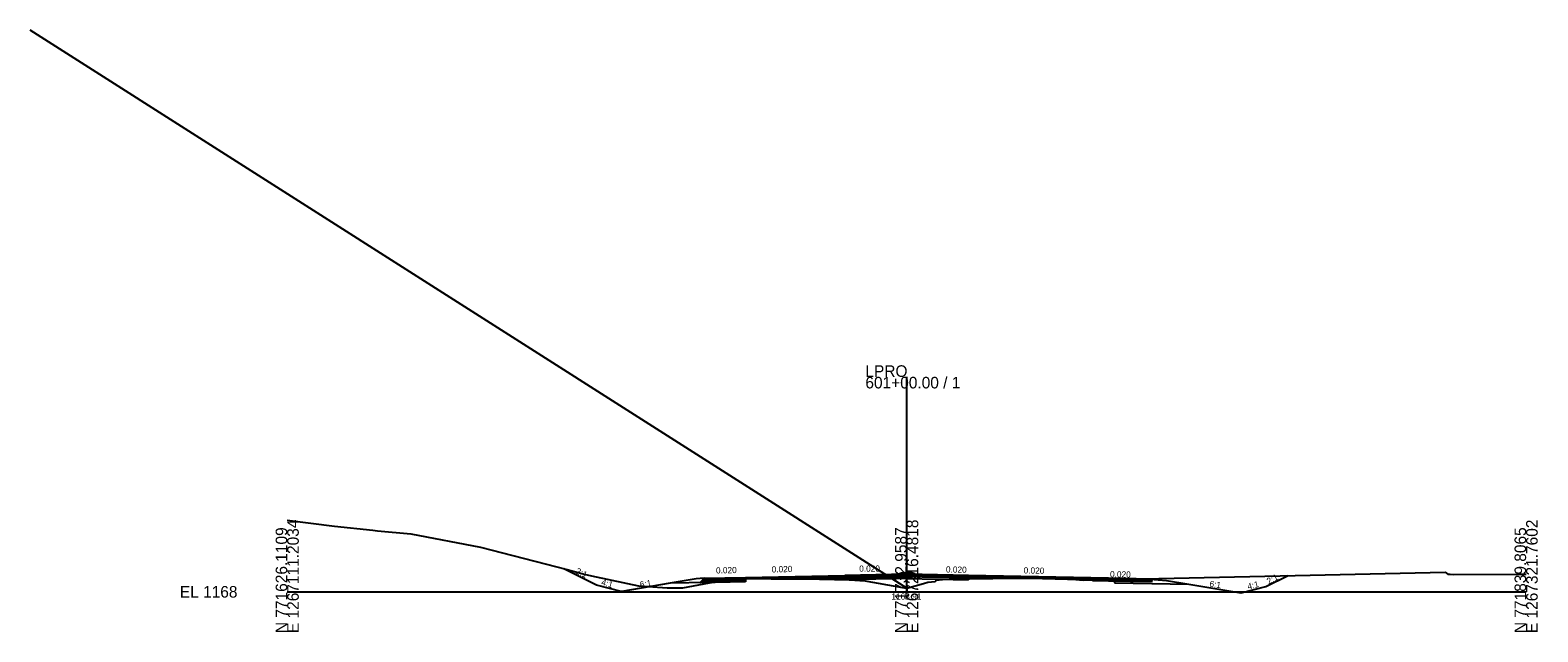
# Model space of a CAD drawing. Extents: x -3833 to 1267678, y -522 to 773248.
# Drawn here: x 937.8 to 1302.8, y 1990.3 to 2136 of the extents above; entities that cross this region are included whole.
import ezdxf

# ---------------------------------------------------------------- set-up
doc = ezdxf.new("R2010")
doc.units = 0
for name, color, linetype in [('Exist Cross Section Cell', 7, 'Continuous'), ('Exist XS Center Line Elevation Label', 7, 'Continuous'), ('Exist XS Ground Line', 7, 'Continuous'), ('Prop CMT DNC', 7, 'Continuous'), ('Prop CMT Pvmt Course 1', 7, 'Continuous'), ('Prop CMT Pvmt Course 2', 7, 'Continuous'), ('Prop CMT Pvmt Course 4', 7, 'Continuous'), ('Prop CMT Shld Paved Course 1', 7, 'Continuous'), ('Prop CMT Shld Paved Course 2', 7, 'Continuous'), ('Prop CMT Shld Paved Course 4', 7, 'Continuous'), ('Prop CMT Slope Grass', 7, 'Continuous'), ('Prop CMT Subgrade Earthwork', 7, 'Continuous'), ('Prop Conc Curb and Gutter', 7, 'Continuous'), ('Prop Corridor Mesh Bottom', 7, 'Continuous'), ('Prop XS Ditch Slope Text', 7, 'Continuous'), ('Prop XS Finish Grade', 7, 'Continuous'), ('Prop XS SE Text', 7, 'Continuous'), ('Scratch_Level_1', 7, 'Continuous')]:
    doc.layers.add(name, color=color, linetype=linetype)

msp = doc.modelspace()

# ---------------------------------------------------------------- linework, layer by layer
at = {"layer": 'Exist Cross Section Cell'}
for p, q in [((1150, 2000), (1150, 2052.04)), ((1000, 2000), (1150, 2000)), ((1150, 2000), (1300, 2000))]:
    msp.add_line(p, q, dxfattribs=at)
at = {"layer": 'Exist XS Ground Line'}
for p, q in [((1000, 2017.35), (1011.44, 2015.88)), ((1011.44, 2015.88), (1020.77, 2014.9)), ((1020.77, 2014.9), (1021.86, 2014.79)), ((1021.86, 2014.79), (1029.97, 2014.07)), ((1029.97, 2014.07), (1046.78, 2010.8)), ((1046.78, 2010.8), (1067.76, 2005.37)), ((1067.76, 2005.37), (1072.22, 2004.2)), ((1244.09, 2003.95), (1280.38, 2004.73)), ((1280.38, 2004.73), (1281.05, 2004.27)), ((1072.22, 2004.2), (1074.82, 2003.59)), ((1074.82, 2003.59), (1085.03, 2001.42)), ((1085.03, 2001.42), (1092.03, 2001)), ((1092.03, 2001), (1095.8, 2000.95)), ((1095.8, 2000.95), (1100.99, 2001.9)), ((1100.99, 2001.9), (1106.65, 2003)), ((1106.65, 2003), (1108.56, 2003.11)), ((1108.56, 2003.11), (1110.7, 2003.22)), ((1110.7, 2003.22), (1117.21, 2003.18)), ((1117.21, 2003.18), (1122.68, 2003.14)), ((1122.68, 2003.14), (1128.9, 2003.02)), ((1128.9, 2003.02), (1136.08, 2002.89)), ((1136.08, 2002.89), (1137.47, 2002.83)), ((1137.47, 2002.83), (1138.69, 2002.77)), ((1138.69, 2002.77), (1139.47, 2002.73)), ((1139.47, 2002.73), (1148.99, 2001.08)), ((1148.99, 2001.08), (1150.04, 2000.91)), ((1150.04, 2000.91), (1154.1, 2002.03)), ((1154.1, 2002.03), (1155.09, 2002.3)), ((1155.09, 2002.3), (1156.87, 2002.53)), ((1156.87, 2002.53), (1157.17, 2002.85)), ((1157.17, 2002.85), (1158.71, 2002.94)), ((1158.71, 2002.94), (1160.29, 2003.02)), ((1160.29, 2003.02), (1162.74, 2003.09)), ((1162.74, 2003.09), (1164.92, 2003.16)), ((1164.92, 2003.16), (1170.4, 2003.25)), ((1170.4, 2003.25), (1176.81, 2003.34)), ((1176.81, 2003.34), (1179.94, 2003.28)), ((1179.94, 2003.28), (1188.92, 2003.09)), ((1188.92, 2003.09), (1190.93, 2002.96)), ((1190.93, 2002.96), (1192.71, 2002.85)), ((1192.71, 2002.85), (1244.09, 2003.95)), ((1281.05, 2004.27), (1281.6, 2004.26)), ((1281.6, 2004.26), (1282.41, 2004.21)), ((1282.41, 2004.21), (1298.02, 2004.28)), ((1298.02, 2004.28), (1300, 2004.3))]:
    msp.add_line(p, q, dxfattribs=at)
at = {"layer": 'Prop CMT Pvmt Course 1'}
for p, q in [((1111, 2003.47), (1135, 2003.95)), ((1135, 2003.7), (1111, 2003.22)), ((1111, 2003.22), (1111, 2003.47)), ((1111, 2003.47), (1111, 2003.47)), ((1135, 2003.95), (1135, 2003.95)), ((1135, 2003.95), (1135, 2003.95)), ((1135, 2003.95), (1135, 2003.7)), ((1135, 2003.7), (1135, 2003.7)), ((1147.75, 2004.21), (1147, 2004.19)), ((1147, 2003.94), (1147.75, 2003.96)), ((1152.25, 2004.21), (1152.82, 2004.2)), ((1152.82, 2003.95), (1152.25, 2003.96)), ((1152.82, 2004.2), (1153, 2004.19)), ((1153, 2003.94), (1152.82, 2003.95)), ((1198.91, 2003.27), (1165, 2003.95)), ((1165, 2003.95), (1165, 2003.95)), ((1165, 2003.95), (1165, 2003.7)), ((1165, 2003.7), (1195, 2003.1)), ((1165, 2003.7), (1165, 2003.7)), ((1195, 2003.1), (1195, 2003.35)), ((1195, 2003.35), (1195, 2003.35)), ((1195, 2003.35), (1198.91, 2003.27)), ((1198.91, 2003.27), (1198.91, 2003.27)), ((1198.91, 2003.27), (1198.91, 2003.27))]:
    msp.add_line(p, q, dxfattribs=at)
at = {"layer": 'Prop CMT Pvmt Course 2'}
for p, q in [((1150, 2004), (1135, 2003.7)), ((1135, 2003.7), (1135, 2003.7)), ((1135, 2003.7), (1135, 2003.37)), ((1135, 2003.37), (1150, 2003.67)), ((1135, 2003.37), (1135, 2003.37)), ((1147.75, 2003.96), (1147, 2003.94)), ((1165, 2003.7), (1150, 2004)), ((1150, 2004), (1150, 2004)), ((1150, 2004), (1150, 2004)), ((1150, 2003.67), (1150, 2003.67)), ((1150, 2003.67), (1150, 2003.67)), ((1150, 2003.67), (1165, 2003.37)), ((1152.25, 2003.96), (1152.82, 2003.95)), ((1152.82, 2003.95), (1153, 2003.94)), ((1165, 2003.37), (1165, 2003.7)), ((1165, 2003.7), (1165, 2003.7)), ((1165, 2003.37), (1165, 2003.37)), ((1195, 2003.1), (1195, 2002.77)), ((1198.91, 2003.02), (1195, 2003.1)), ((1195, 2002.77), (1198.91, 2002.69)), ((1198.91, 2002.69), (1198.91, 2003.02))]:
    msp.add_line(p, q, dxfattribs=at)
at = {"layer": 'Prop CMT Pvmt Course 4'}
for p, q in [((1135, 2003.37), (1150, 2003.67)), ((1135, 2003.37), (1135, 2003.37)), ((1135, 2003.37), (1135, 2003.37)), ((1147.01, 2004.19), (1147.01, 2003.15)), ((1148.01, 2004.21), (1148.01, 2003.17)), ((1150, 2003.67), (1150, 2003.67)), ((1150, 2003.67), (1150, 2003.67)), ((1150, 2003.67), (1165, 2003.37)), ((1152.01, 2004.21), (1152.01, 2003.17)), ((1153.01, 2004.19), (1153.01, 2003.15)), ((1165, 2003.37), (1165, 2003.37)), ((1165, 2003.37), (1165, 2003.37))]:
    msp.add_line(p, q, dxfattribs=at)
at = {"layer": 'Prop CMT Shld Paved Course 1'}
for p, q in [((1100.74, 2003.02), (1101, 2003.27)), ((1111, 2003.22), (1100.74, 2003.02)), ((1101, 2003.27), (1111, 2003.47)), ((1101, 2003.27), (1101, 2003.27)), ((1111, 2003.47), (1111, 2003.47)), ((1111, 2003.47), (1111, 2003.47)), ((1111, 2003.47), (1111, 2003.22)), ((1111, 2003.22), (1111, 2003.22)), ((1150, 2004.25), (1135, 2003.95)), ((1135, 2003.7), (1150, 2004)), ((1135, 2003.95), (1135, 2003.95)), ((1135, 2003.95), (1135, 2003.7)), ((1165, 2003.95), (1150, 2004.25)), ((1150, 2004.25), (1150, 2004.25)), ((1150, 2004.25), (1150, 2004.25)), ((1150, 2004), (1150, 2004)), ((1150, 2004), (1150, 2004)), ((1150, 2004), (1165, 2003.7)), ((1150, 2003.94), (1150, 2003.94)), ((1165, 2003.7), (1165, 2003.95)), ((1165, 2003.95), (1165, 2003.95)), ((1198.91, 2003.27), (1198.91, 2003.02)), ((1208.91, 2003.07), (1198.91, 2003.27)), ((1198.91, 2003.02), (1209.17, 2002.82)), ((1209.17, 2002.82), (1208.91, 2003.07))]:
    msp.add_line(p, q, dxfattribs=at)
at = {"layer": 'Prop CMT Shld Paved Course 2'}
for p, q in [((1100.4, 2002.68), (1100.74, 2003.02)), ((1111, 2002.89), (1100.4, 2002.68)), ((1100.74, 2003.02), (1111, 2003.22)), ((1100.74, 2003.02), (1100.74, 2003.02)), ((1117.21, 2003.35), (1111, 2003.22)), ((1111, 2003.22), (1111, 2003.22)), ((1111, 2003.22), (1111, 2003.22)), ((1111, 2003.22), (1111, 2003.22)), ((1111, 2003.22), (1111, 2003.22)), ((1111, 2003.22), (1111, 2003.22)), ((1111, 2003.22), (1117.21, 2003.18)), ((1111, 2002.89), (1111, 2002.89)), ((1122.67, 2003.46), (1117.21, 2003.35)), ((1117.21, 2003.35), (1117.21, 2003.35)), ((1117.21, 2003.18), (1117.21, 2003.18)), ((1117.21, 2003.18), (1122.67, 2003.14)), ((1128.9, 2003.58), (1122.67, 2003.46)), ((1122.67, 2003.14), (1122.67, 2003.14)), ((1122.67, 2003.14), (1123.18, 2003.13)), ((1123.18, 2003.13), (1128.9, 2003.25)), ((1135, 2003.7), (1128.9, 2003.58)), ((1128.9, 2003.58), (1128.9, 2003.58)), ((1128.9, 2003.25), (1135, 2003.37)), ((1128.9, 2003.25), (1128.9, 2003.25)), ((1135, 2003.7), (1135, 2003.7)), ((1170.4, 2003.59), (1165, 2003.7)), ((1165, 2003.7), (1165, 2003.7)), ((1165, 2003.7), (1165, 2003.16)), ((1165, 2003.37), (1170.4, 2003.26)), ((1176.81, 2003.47), (1170.4, 2003.59)), ((1170.4, 2003.59), (1170.4, 2003.59)), ((1170.4, 2003.26), (1170.4, 2003.26)), ((1170.4, 2003.26), (1170.85, 2003.25)), ((1170.85, 2003.25), (1176.81, 2003.34)), ((1179.94, 2003.4), (1176.81, 2003.47)), ((1176.81, 2003.47), (1176.81, 2003.47)), ((1176.81, 2003.47), (1176.81, 2003.47)), ((1176.81, 2003.34), (1176.81, 2003.34)), ((1176.81, 2003.34), (1176.81, 2003.34)), ((1176.81, 2003.34), (1176.81, 2003.34)), ((1176.81, 2003.34), (1179.94, 2003.28)), ((1188.92, 2003.22), (1179.94, 2003.4)), ((1179.94, 2003.4), (1179.94, 2003.4)), ((1179.94, 2003.28), (1179.94, 2003.28)), ((1179.94, 2003.28), (1188.92, 2003.09)), ((1190.93, 2003.18), (1188.92, 2003.22)), ((1188.92, 2003.22), (1188.92, 2003.22)), ((1188.92, 2003.09), (1188.92, 2003.09)), ((1188.92, 2003.09), (1190.93, 2002.96)), ((1192.71, 2003.15), (1190.93, 2003.18)), ((1190.93, 2003.18), (1190.93, 2003.18)), ((1190.93, 2002.96), (1190.93, 2002.96)), ((1190.93, 2002.96), (1192.71, 2002.85)), ((1195, 2003.1), (1192.71, 2003.15)), ((1192.71, 2003.15), (1192.71, 2003.15)), ((1192.71, 2002.85), (1195, 2002.9)), ((1192.71, 2002.85), (1192.71, 2002.85)), ((1192.71, 2002.85), (1192.71, 2002.85)), ((1192.71, 2002.85), (1192.71, 2002.85)), ((1195, 2002.9), (1195, 2003.1)), ((1195, 2003.1), (1195, 2003.1)), ((1195, 2003.1), (1195, 2003.1)), ((1195, 2002.9), (1195, 2002.9)), ((1198.91, 2003.02), (1198.91, 2002.69)), ((1209.17, 2002.82), (1198.91, 2003.02)), ((1198.91, 2002.69), (1209.5, 2002.48)), ((1209.5, 2002.48), (1209.17, 2002.82))]:
    msp.add_line(p, q, dxfattribs=at)
at = {"layer": 'Prop CMT Shld Paved Course 4'}
for p, q in [((1099.94, 2002.21), (1100.4, 2002.68)), ((1111, 2002.43), (1099.94, 2002.21)), ((1100.4, 2002.68), (1100.9, 2002.69)), ((1100.9, 2002.69), (1111, 2002.89)), ((1111, 2002.89), (1111, 2002.43)), ((1200.3, 2002.67), (1200.3, 2002.21)), ((1200.3, 2002.21), (1200.3, 2002.21))]:
    msp.add_line(p, q, dxfattribs=at)
at = {"layer": 'Prop CMT Slope Grass'}
for p, q in [((1099, 2003.11), (1092.72, 2002.07)), ((1101, 2003.27), (1099, 2003.11)), ((1208.91, 2003.07), (1212.91, 2002.75)), ((1212.91, 2002.75), (1218.36, 2001.85))]:
    msp.add_line(p, q, dxfattribs=at)
at = {"layer": 'Prop CMT Subgrade Earthwork'}
for p, q in [((1111, 2002.43), (1092.72, 2002.07)), ((1111, 2003.22), (1111, 2002.43)), ((1150.01, 2003.21), (1135.04, 2002.91)), ((1149.99, 2003.21), (1165, 2002.91)), ((1165, 2003.16), (1165, 2002.91)), ((1200.3, 2003.01), (1200.3, 2002.21)), ((1200.3, 2002.21), (1218.36, 2001.85))]:
    msp.add_line(p, q, dxfattribs=at)
at = {"layer": 'Prop Conc Curb and Gutter'}
for p, q in [((1148, 2004.17), (1148.01, 2004.34)), ((1148.01, 2004.34), (1148.76, 2004.59)), ((1148.76, 2004.59), (1150.01, 2004.61)), ((1151.25, 2004.58), (1150.01, 2004.61)), ((1152, 2004.33), (1151.25, 2004.58)), ((1148, 2004.17), (1148, 2004.04)), ((1148, 2004.04), (1150.01, 2004.04)), ((1152.01, 2004.04), (1150.01, 2004.04)), ((1152.01, 2004.17), (1152, 2004.33)), ((1152.01, 2004.17), (1152.01, 2004.04))]:
    msp.add_line(p, q, dxfattribs=at)
at = {"layer": 'Prop Corridor Mesh Bottom'}
for p, q in [((1111, 2003.47), (1111, 2003.22)), ((1135, 2003.95), (1135, 2003.7)), ((1165, 2003.95), (1165, 2003.7)), ((1198.91, 2003.27), (1198.91, 2003.02))]:
    msp.add_line(p, q, dxfattribs=at)
at = {"layer": 'Prop XS Finish Grade'}
for p, q in [((1074.9, 2001.61), (1066.98, 2005.57)), ((1080.9, 2000.11), (1074.9, 2001.61)), ((1092.72, 2002.07), (1081, 2000.11)), ((1208.91, 2003.07), (1212.91, 2002.75)), ((1218.36, 2001.85), (1230.91, 1999.75)), ((1231.01, 1999.75), (1237.01, 2001.25)), ((1237.01, 2001.25), (1242.34, 2003.92)), ((1080.95, 2000.11), (1080.9, 2000.11)), ((1081, 2000.11), (1080.95, 2000.11)), ((1230.91, 1999.75), (1230.96, 1999.75)), ((1230.96, 1999.75), (1231.01, 1999.75))]:
    msp.add_line(p, q, dxfattribs=at)
at = {"layer": 'Scratch_Level_1'}
msp.add_line((1150, 2000.91), (937.75, 2135.97), dxfattribs=at)

# ---------------------------------------------------------------- texts
at = {"layer": 'Exist Cross Section Cell'}
for s, p in [('601+00.00 / 1', (1140, 2049.24)), ('LPRO', (1140, 2052.04)), ('EL 1168', (974, 1998.6))]:
    msp.add_text(s, height=2.8, dxfattribs=at).set_placement(p)
for s, p in [('N 771626.1109', (1000, 1990)), ('E 1267111.2034', (1002.8, 1990)), ('N 771732.9587', (1150, 1990)), ('E 1267216.4818', (1152.8, 1990)), ('N 771839.8065', (1300, 1990)), ('E 1267321.7602', (1302.8, 1990))]:
    msp.add_text(s, height=2.8, rotation=90, dxfattribs=at).set_placement(p)
at = {"layer": 'Exist XS Center Line Elevation Label'}
msp.add_text('1168.91', height=1.5, dxfattribs=at).set_placement((1146.3, 1998.12))
at = {"layer": 'Prop CMT DNC'}
for p in [(1062.18, 2006.81), (1101, 2003.27), (1111, 2003.47), (1111, 2003.47), (1135, 2003.95), (1135, 2003.95), (1165, 2003.95), (1165, 2003.95), (1198.91, 2003.27), (1198.91, 2003.27), (1208.91, 2003.07), (1242.34, 2003.92), (1080.95, 2000.11), (1081, 2000.11), (1230.91, 1999.75), (1230.96, 1999.75)]:
    msp.add_text('X', height=0.00025, dxfattribs=at).set_placement(p)
at = {"layer": 'Prop XS Ditch Slope Text'}
for s, rotation, p in [('2:1', 334.1731, (1069.7, 2004.53)), ('4:1', 343.7547, (1075.94, 2001.7)), ('6:1', 9.0286, (1085.51, 2001)), ('6:1', 352.0901, (1223.25, 2001.23)), ('4:1', 13.9045, (1232.71, 2000.52)), ('2:1', 27.7802, (1237.67, 2001.79))]:
    msp.add_text(s, height=1.5, rotation=rotation, dxfattribs=at).set_placement(p)
at = {"layer": 'Prop XS SE Text'}
for rotation, p in [(1.397, (1103.84, 2004.42)), (1.397, (1117.33, 2004.67)), (0.2693, (1138.51, 2004.86)), (358.8542, (1159.5, 2004.68)), (358.8542, (1178.31, 2004.45)), (358.8542, (1199.23, 2003.53))]:
    msp.add_text('0.020', height=1.5, rotation=rotation, dxfattribs=at).set_placement(p)

doc.saveas('drawing.dxf')
